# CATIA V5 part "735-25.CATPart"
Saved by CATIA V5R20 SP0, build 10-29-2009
Part number: 735-25
Bounding box of the stored display mesh (mm): x -24 to 24, y -23.94 to 23.94, z -23 to 36
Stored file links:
  C:\Users\Utente\Desktop\IO LAVORO\3D X SITO CF\X SITO\735\735-25.CATPart
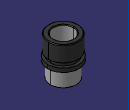
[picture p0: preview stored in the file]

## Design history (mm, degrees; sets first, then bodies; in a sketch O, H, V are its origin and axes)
Set1
  DatumSurface1 to DatumSurface25 "735-25"
Body1 (main body)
